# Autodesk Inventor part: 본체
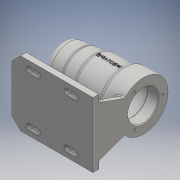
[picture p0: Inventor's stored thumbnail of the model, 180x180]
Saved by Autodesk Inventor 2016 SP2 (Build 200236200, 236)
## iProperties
Created: 2017-09
Part Number: 본체
Material: Generic
Document SubType Name: Modeling
Designer: Administrator
Density: 1 g/cm^3
Appearance: Default
Author: Administrator
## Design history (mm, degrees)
sketch "스케치1"
  geometry: L1 (-56, 45)-(56, 45); L2 (56, 45)-(56, -45); L3 (56, -45)-(-56, -45); L4 (-56, -45)-(-56, 45); L5 (-56, 45)-(56, -45); L6 (56, 45)-(-56, -45); 1 further point
  constraints: 12 end point, 2 midpoint, 2 parallel, 1 horizontal, 1 perpendicular
  dimensions: "d0" = 112 distance of L2.end L3.end; "d1" = 90 distance of L1.end L2.end
extrude "돌출1" new body sketch "스케치1" distance "d2" = 8; taper "d3" = 0 deg
sketch "스케치2"
  geometry: L1 (-56, -45)-(56, -45) reference; L2 (56, -45)-(56, 45) reference; L3 (56, 45)-(-56, 45) reference; L4 (-56, 45)-(-56, -45) reference; L5 (56, 45)-(-56, 45) reference; L6 (-56, -45)-(56, -45) reference; L7 (-32, -30)-(-20, -30); L8 (-20, -38)-(-32, -38); L9 (20, -30)-(32, -30); L10 (32, -38)-(20, -38); A1 r 4 centre (20, -34) between (20, -30) and (20, -38); A2 r 4 centre (32, -34) between (32, -38) and (32, -30); A3 r 4 centre (-20, -34) between (-20, -38) and (-20, -30); A4 r 4 centre (-32, -34) between (-32, -30) and (-32, -38); 5 further points
  constraints: 8 end point, 8 point on circle, 4 centre point, 2 coincident, 2 horizontal, 2 midpoint, 2 parallel, 1 collinear, 1 horizontal alignment, 1 point on line, 1 tangent
  dimensions: "d4" = 8 diameter of A1; "d5" = 8 diameter of A2; "d6" = 8 diameter of A3; "d7" = 8 diameter of A4; "d13" = 24 distance from line of A2.centre L2; "d14" = 12 distance of point (20, -34) A2.centre; "d15" = 40 distance of A3.centre point (20, -34); "d16" = 12 distance of point (-32, -34) A3.centre; "d17" = 34 vertical distance of A4.centre point (0, 0); "d19" = 8 distance between parallel lines of L8 L7
extrude "돌출2" cut sketch "스케치2" stored distance "d20" = 8; taper "d21" = 0 deg
chamfer "모따기1" distance "d22" = 12; stored, may be unused: second distance "d23" = 2, angle "d24" = 45 deg
sketch "스케치3"
  geometry: L1 (-56.618, 70)-(56, 70); L2 (56, 0)-(56, 8) reference; L3 (56, 70)-(56, 104); L4 (56, 104)-(28, 104); L5 (28, 104)-(28, 100); L6 (28, 100)-(-11, 100); L7 (-11, 100)-(-11, 97); L8 (-11, 97)-(-31, 97); L9 (-31, 97)-(-31, 95); L10 (-31, 95)-(-56, 95); L11 (-56, 95)-(-56, 70); 2 further points
  constraints: 20 end point, 8 perpendicular, 1 horizontal, 1 midpoint, 1 point on line, 1 vertical, 1 vertical alignment
  dimensions: "d26" = 70 vertical distance of point (0, 0) L1.start; "d27" = 112 distance between parallel lines of L11 L3; "d28" = 84 distance between parallel lines of L11 L5; "d29" = 45 distance between parallel lines of L11 L7; "d30" = 25 distance between parallel lines of L11 L9; "d31" = 50 diameter of L10 L1; "d32" = 54 diameter of L8 L1; "d33" = 60 diameter of L6 L1; "d34" = 68 diameter of L4 L1
revolve "회전1" sketch "스케치3" stored, may be unused: angle "d35" = 90 deg
sketch "스케치4"
  geometry: L1 (-56, 45)-(-56, 95) reference; L2 (56, 36)-(56, 104) reference; L3 (-56, 70)-(56, 70); L4 (56, 91)-(41, 91); L5 (41, 91)-(41, 94); L6 (41, 94)-(-13, 94); L7 (-13, 94)-(-13, 91); L8 (-13, 91)-(-25, 91); L9 (-25, 91)-(-25, 87.5); L10 (-25, 87.5)-(-43, 87.5); L11 (-43, 87.5)-(-43, 86); L12 (-43, 86)-(-47, 86); L13 (-47, 86)-(-47, 80.5); L14 (-47, 80.5)-(-50, 80.5); L15 (-50, 80.5)-(-50, 70); 1 further point
  constraints: 26 end point, 11 perpendicular, 4 point on line, 2 midpoint
  dimensions: "d36" = 15 distance of L4.start L4.end; "d37" = 54 distance of L5.end L6.end; "d38" = 12 distance of L7.end L8.end; "d39" = 18 distance of L9.end L10.end; "d40" = 4 distance of L11.end L12.end; "d41" = 3 distance of L13.end L14.end; "d42" = 42 diameter of L4 L3; "d43" = 48 diameter of L6 L3; "d44" = 35 diameter of L10 L3; "d45" = 32 diameter of L12 L3; "d46" = 21 diameter of L14 L3
revolve "회전2" sketch "스케치4" stored, may be unused: angle "d47" = 90 deg
sketch "스케치5"
  geometry: L1 (0, 0)-(0, 39.878); L2 (0, 0)-(-35.783, -20.659); L3 (0, 0)-(39.926, -23.051); C1 r 34 at (0, 0) reference; A1 r 26 centre (0, 0) between (0, 26) and (-22.517, -13); 2 further points
  constraints: 6 end point, 3 point on circle, 2 point on line, 1 centre point, 1 coincident, 1 vertical, 1 vertical alignment
  dimensions: "d48" = 52 diameter of A1; "d49" = 120 deg angle of L2 L1; "d50" = 120 deg angle of L3 L1
hole "구멍1" sketch "스케치5" at (0, 26), (-22.517, -13), (22.517, -13) diameter "d51" = 3.242; stored, may be unused: countersink angle "d55" = 90 deg, drill point angle "d57" = 118 deg; dims "d52" = 8, "d53" = 4, "d54" = 2, "d56" = 11
node "작업 평면1"
sketch "스케치7"
  geometry: L1 (8, 45)-(8, -45) reference; L2 (43.992, 21.9)-(8, 35); L3 (8, -33)-(8, 33) reference; L4 (43.992, -21.9)-(8, -35); L5 (0, 45)-(8, 45) reference; L6 (0, -45)-(8, -45) reference; L7 (0, 0)-(70, 0); L8 (8, 35)-(8, -35); L9 (0, 33)-(0, -33) reference; A1 r 34 centre (70, 0) between (43.992, 21.9) and (43.992, -21.9) reference
  constraints: 8 end point, 2 point on circle, 2 point on line, 1 equal length, 1 horizontal, 1 parallel
  dimensions: "d63" = 10 distance from line of L5 L2.end; "d64" = 10 distance from line of L6 L4.end; "d67" = 110 deg angle of L4 L1
extrude "돌출3" join sketch "스케치7" distance "d68" = 8; taper "d69" = 0 deg
sketch "스케치8"
  geometry: L1 (-44, 8)-(-44, 0) reference; L2 (56, 8)-(-44, 8) reference; L3 (56, 0)-(56, 8) reference; L4 (-44, 0)-(56, 0) reference; L5 (-56, 45)-(-31, 45) reference; L6 (-31, 43)-(-11, 43) reference; L7 (-11, 40)-(28, 40) reference; L8 (28, 36)-(48, 36) reference; L9 (28, 36)-(28, 104) reference; L10 (-11, 43)-(-11, 97) reference; L11 (-11, 40)-(-11, 100) reference; L12 (-31, 43)-(-31, 97) reference; L13 (56, 8)-(-44, 8) reference; L14 (-56, 0)-(-56, 8) reference; L15 (-34, 8)-(-23.014, 49); L16 (-32, 8)-(-20, 8) reference; L17 (48, 8)-(56, 8) reference; L18 (48, 8)-(-34, 8); L19 (-13, 94)-(-13, 46) reference; L20 (41, 94)-(41, 46) reference; L21 (-13, 49)-(-25, 49) reference; L22 (41, 45)-(-31, 45); 2 further points
  constraints: 6 end point, 5 point on line, 1 horizontal
  dimensions: "d75" = 105 deg angle of L2 L15; "d77" = 22 distance from line of L14 L15.start; "d86" = 41 vertical distance of L15.start L15.end
  node "투영된 루프2"
  node "투영된 루프3"
fillet "모깎기1" dims "d81" = 0.3
fillet "모깎기2" dims "d82" = 9
fillet "모깎기5" dims "d85" = 3
feature "리브1" dims "d87" = 1, "d88" = 8, "d89" = 0, "d90" = 0, "d91" = 1, "d92" = 1
fillet "모깎기6" dims "d93" = 3
fillet "모깎기7" dims "d94" = 3
fillet "모깎기11" dims "d98" = 3
fillet "모깎기12" dims "d99" = 3
fillet "모깎기13" dims "d100" = 3
node "작업 평면2"
sketch "스케치9"
  geometry: L1 (56, 45.289)-(56, 104) reference; L2 (-56, 54)-(-56, 86) reference; 3 further points
  constraints: 1 horizontal alignment, 1 midpoint, 1 other
  dimensions: "d102" = 48 distance from line of point (8, 70) L1
feature "엠보싱1" sketch "스케치9" dims "d0" = 112, "d1" = 90, "d4" = 8, "d5" = 8, "d6" = 8, "d7" = 8, "d13" = 24, "d14" = 12, "d15" = 40, "d16" = 12, "d17" = 34, "d19" = 8, "d103" = 0.5, "d104" = 0
chamfer "모따기2" distance "d105" = 1; stored, may be unused: second distance "d106" = 2, angle "d107" = 45 deg
fillet "모깎기14" dims "d108" = 3
fillet "모깎기15" dims "d109" = 3
node "솔리드1"
mirror "대칭1"
node "투영된 루프1"
other parameters: "d62" = 56
